(* Logix 5000 project; controller Test vendor 1 type 14 code 92 rev 33.11; software revision 33.00 *)

TASK MainTask (continuous, watchdog 500 ms) : MainProgram

MODULES
   Local : vendor 1 type 14 code 92 (ICP 0, rev 33.11)
      IN : vendor 1 type 7 code 1 (ICP 3, rev 3.2, Input RPI 20 ms)
      O : vendor 1 type 7 code 15 (ICP 2, rev 3.2, Output RPI 20 ms)
      Ethernet : 1756-ENBT (ICP 1, Ethernet 192.168.0.98, rev 6.4)
         IOLM1 : DXM (Ethernet 192.168.0.12, rev 2.22, StandardDataDriven RPI 20 ms)
END_MODULES

TYPE Banner_IOL_Port_v4 :   // UDT that has all of the data items necessary to communicate with a specific Port on a IO-Link Master
STRUCT
   Port_Controlled : INT;   // Each bit represents a port on an IO-Link Master. Set to 1 to tell AOI to control that port.
   Port_Activate : INT;   // Each bit represents a port on an IO-Link Master. When ON that port will process any commands in queue.
   Port_Read : INT;   // Each bit represents a port on an IO-Link Master. Used to determine when device AOI has requested a Read command.
   Port_Write : INT;   // Each bit represents a port on an IO-Link Master. Used to determine when device AOI has requested a Write command.
   Port_RW_Complete : INT;   // Each bit represents a port on an IO-Link Master. Tells device AOI that Read or Write request has been completed.
   Port_Device_Read : INT;
   Data_Transfer : SINT[190];   // Array to transfer data from IO-Master to device AOIs.
END_STRUCT
END_TYPE

TYPE Banner_IOLM_EL_v4 :   // Error Log for Messages to IOLM.
STRUCT
   RW : SINT;   // 0 = Read, 1 = Write.
   Port : SINT;   // Port number that generated error.
   Index : INT;   // IO-Link Index for generated error.
END_STRUCT
END_TYPE

TYPE Banner_IOLM_v4 :   // UDT to control IO-Link Masters.
STRUCT
   Message_Source_Data : SINT[190];
   Message_Destination_Data : SINT[190];
   Error_Log : Banner_IOLM_EL_v4[10];
   Error_Write_Retry : BOOL;
   Num_Error_MSGS : DINT;
   IO_Link_Master_Busy : BOOL;   // 0 = While waiting for a command, 1 = Processing command
   AOI_Reset : BOOL;
   Port_Data : Banner_IOL_Port_v4;   // All of the necessary data to work with the various ports of the IO-Link Master.
   Halt_Operation : BOOL;   // When parameter is 1 the AOI is halted as next available time frame.
   AOI_Halted : BOOL;   // AOI is in standby mode until Halt Operation tag is set back to 0.
END_STRUCT
END_TYPE

TYPE Banner_S15C_MGN_PDIO_v4 :   // UDT with all of the variables needed to control an IO-Link S15C MGN.
STRUCT
   Read : Banner_S15C_MGN_Read_DS_v4;   // English Data Set
   Write : Banner_S15C_MGN_Write_DS_v4;   // Metric Data Set
   DTI : SINT[32];   // Array with Raw Process data being transferred into AOI.
   DTO : SINT[32];   // Array with Raw Process data being transferred into AOI.
END_STRUCT
END_TYPE

TYPE Banner_S15C_MGN_RD_v4 :   // All of the read parameters for a S15C.
STRUCT
   Master_Cycle_Time : INT;
   Min_Cycle_Time : INT;
   M_Sequence_Capability : INT;
   IO_Link_Version_ID : INT;
   Process_Data_Input_Length : INT;
   Process_Data_Output_Length : INT;
   Combined_Vendor_ID : DINT;   // IO-Link Vendor ID
   Vendor_ID1 : INT;
   Vendor_ID2 : INT;
   Combined_Device_ID : DINT;   // IO-Link Device ID
   Device_ID1 : INT;
   Device_ID2 : INT;
   Device_ID3 : INT;
   Serial_Number : STRING;
   Product_Name : STRING;
END_STRUCT
END_TYPE

TYPE Banner_S15C_MGN_Read_DS_v4 :
STRUCT
   Read_Data_Set : SINT;
   Read_Success : SINT;
   Write_Success : SINT;
   Register_Verify : SINT;
   Counter_Value : INT;
   Read_Regs : DINT[16];
END_STRUCT
END_TYPE

TYPE Banner_S15C_MGN_v4 :   // All of the parameters for a S15C.
STRUCT
   Initial_Global_Read : BOOL;   // Determines if all of the IO-Link data has been read into the PLC yet
   Command : INT;   // Value placed in here will activate a read or write to a specifc IO-Link Index
   Read : Banner_S15C_MGN_RD_v4;   // Read Only Data
   Write : Banner_S15C_MGN_WD_v4;   // Write Data
   Archive : Banner_S15C_MGN_WD_v4;   // Archive Data
   Reset : BOOL;   // Resets AOI. This will force a complete parameter read of the sensor.
END_STRUCT
END_TYPE

TYPE Banner_S15C_MGN_WD_v4 :   // UDT that stores the Write Data for a S15C.
STRUCT
   System_Command : INT;   // See IODD file for list of commands that can be activated via the System Command interface
   Parameter_Access_Lock : SINT;   // Write access to all parameters is prohibited while value is 1. Only this parameter can be adjusted when value is 1.
   Data_Storage_Lock : SINT;   // Automatic data storage is disabled when this value is equal to 1. Read access is not affected.
   Local_Parameterization_Lock : SINT;   // Parameterization via local control elements on device is disabled.
   Local_User_Interface_Lock : SINT;   // Operation of local user interface is disabled.
   Modbus_Address : DINT;   // 0 to 255
   Modbus_Baud_Rate : DINT;   // 1 to 65535
   Modbus_Parity : DINT;   // 0 to 2
   Modbus_Stop_Bits : DINT;   // 0 to 2
   Modbus_Compliance_Mode : DINT;   // 0 to 4
   RRS : Banner_S15C_RRSS_v4[4];   // Read Register Sets
   WRS : Banner_S15C_WRSS_v4[16];   // Write Registers Set
END_STRUCT
END_TYPE

TYPE Banner_S15C_MGN_Write_DS_v4 :
STRUCT
   Set_to_Read : SINT;
   Write_Regs : DINT[16];
END_STRUCT
END_TYPE

TYPE Banner_S15C_RRSS_v4 :   // Read Register Set Settings
STRUCT
   MB_Reg : DINT[16];   // Index 1 through 15 are used to store the Modbus Registers
END_STRUCT
END_TYPE

TYPE Banner_S15C_WRSS_v4 :   // Write Register Set Settings
STRUCT
   MB_Reg : DINT;   // Index 1 through 15 are used to store the Modbus registers
   MB_Update_Type : SINT;   // Index 1 through 15 used to store the Modbus registers update type
   MB_Check_Result : SINT;   // Index 1 through 15 used to store the Modbus Check Result
   MB_Write_Cmd_Type : SINT;   // Index 1 through 15 used to store the Write Command type
END_STRUCT
END_TYPE

ADD_ON_INSTRUCTION Banner_DXMR90_IOLM_v4   (* revision 4.1, vendor Banner Engineering *)
// AOI that controls a Banner IO-Link Master with Banner devices.
// Revision note:
// Revised operational order for ISDU write.
VAR_IN_OUT
   IOLM : Banner_IOLM_v4; {required}
END_VAR
VAR
   Lock : DINT; {access None}
   Byte_Length : SINT; {access None}
   Current_Port : INT; {access None}   // Current port to communicate with via the IO-Link Master.
   Timer : TIMER := (PRE := 500); {access None}
   Error_Index : DINT; {access None}
   Timer2 : TIMER := (PRE := 5000); {access None}
   Temp_Index : INT; {access None}
   ErrCount : DINT; {access None}
   Timer4 : TIMER := (PRE := 2000); {access None}
   Timer5 : TIMER := (PRE := 2000); {access None}
   Timer3 : TIMER := (PRE := 2000); {access None}
   Timer6 : TIMER := (PRE := 3000); {access None}
   Timer7 : TIMER := (PRE := 3000); {access None}
END_VAR

ROUTINE Logic   (* ladder *)
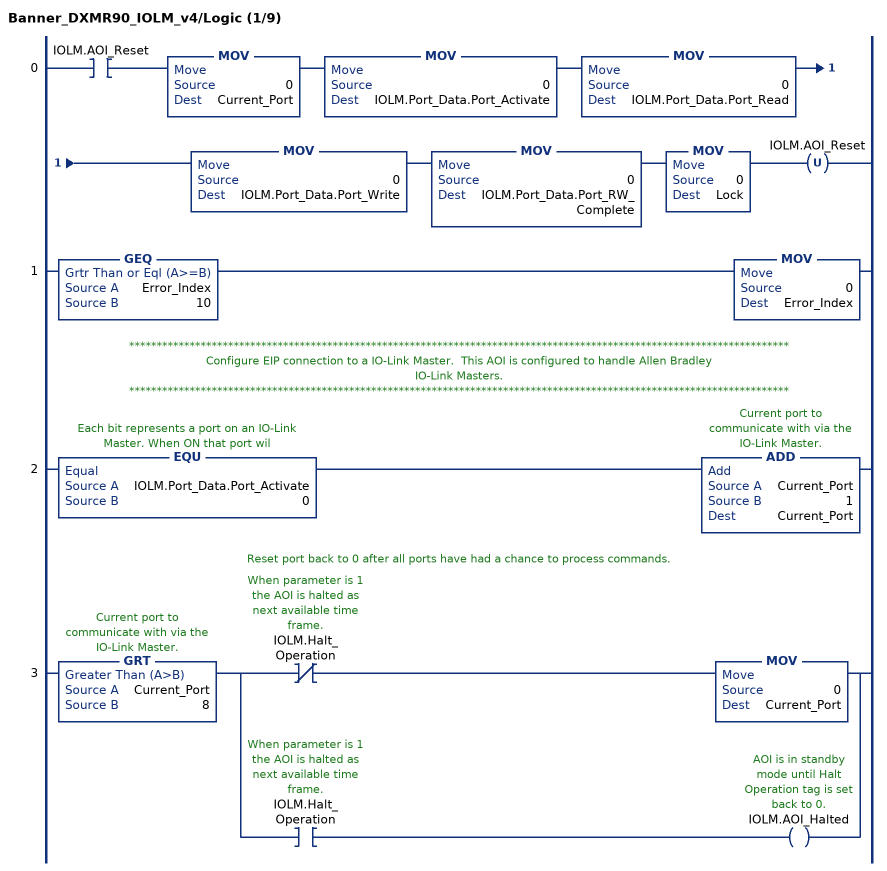
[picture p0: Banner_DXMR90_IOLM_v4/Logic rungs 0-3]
   0: XIC(IOLM.AOI_Reset)MOV(0,Current_Port)MOV(0,IOLM.Port_Data.Port_Activate)MOV(0,IOLM.Port_Data.Port_Read)MOV(0,IOLM.Port_Data.Port_Write)MOV(0,IOLM.Port_Data.Port_RW_Complete)MOV(0,Lock)OTU(IOLM.AOI_Reset);
   1: GEQ(Error_Index,10)MOV(0,Error_Index);
   // ************************************************************************************************************************
   // Configure EIP connection to a IO-Link Master.  This AOI is configured to handle Allen Bradley
   // IO-Link Masters.
   // ************************************************************************************************************************
   2: EQU(IOLM.Port_Data.Port_Activate,0)ADD(Current_Port,1,Current_Port);
   // Reset port back to 0 after all ports have had a chance to process commands.
   3: GRT(Current_Port,8)[XIO(IOLM.Halt_Operation) MOV(0,Current_Port) ,XIC(IOLM.Halt_Operation) OTE(IOLM.AOI_Halted) ];
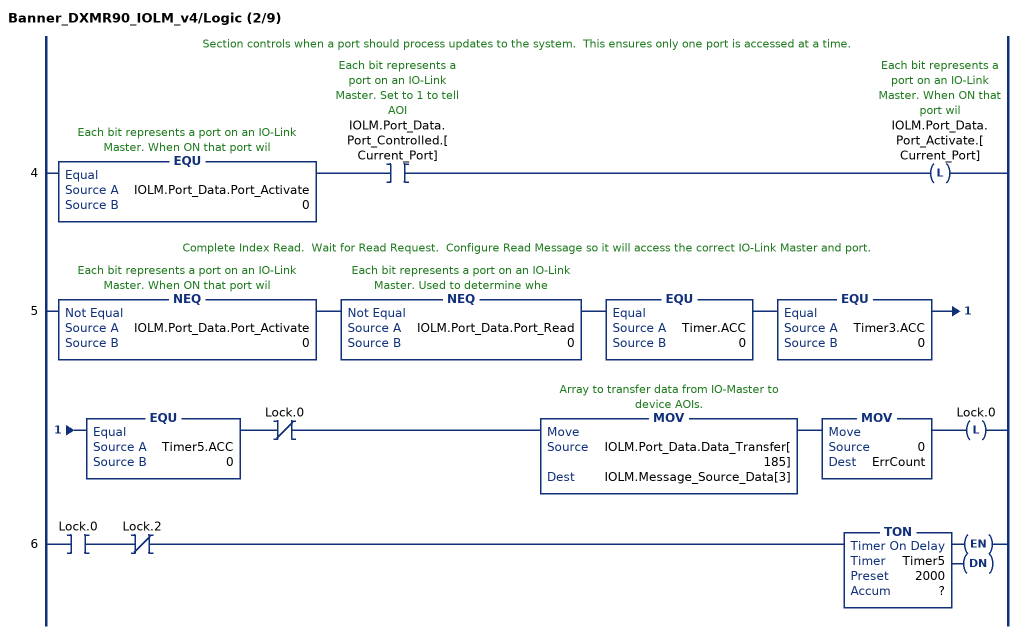
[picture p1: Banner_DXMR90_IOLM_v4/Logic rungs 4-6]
   // Section controls when a port should process updates to the system.  This ensures only one port is accessed at a time.
   4: EQU(IOLM.Port_Data.Port_Activate,0)XIC(IOLM.Port_Data.Port_Controlled.[Current_Port])OTL(IOLM.Port_Data.Port_Activate.[Current_Port]);
   // Complete Index Read.  Wait for Read Request.  Configure Read Message so it will access the correct IO-Link Master and port.
   5: NEQ(IOLM.Port_Data.Port_Activate,0)NEQ(IOLM.Port_Data.Port_Read,0)EQU(Timer.ACC,0)EQU(Timer3.ACC,0)EQU(Timer5.ACC,0)XIO(Lock.0)MOV(IOLM.Port_Data.Data_Transfer[185],IOLM.Message_Source_Data[3])MOV(0,ErrCount)OTL(Lock.0);
   6: XIC(Lock.0)XIO(Lock.2)TON(Timer5,?,?);
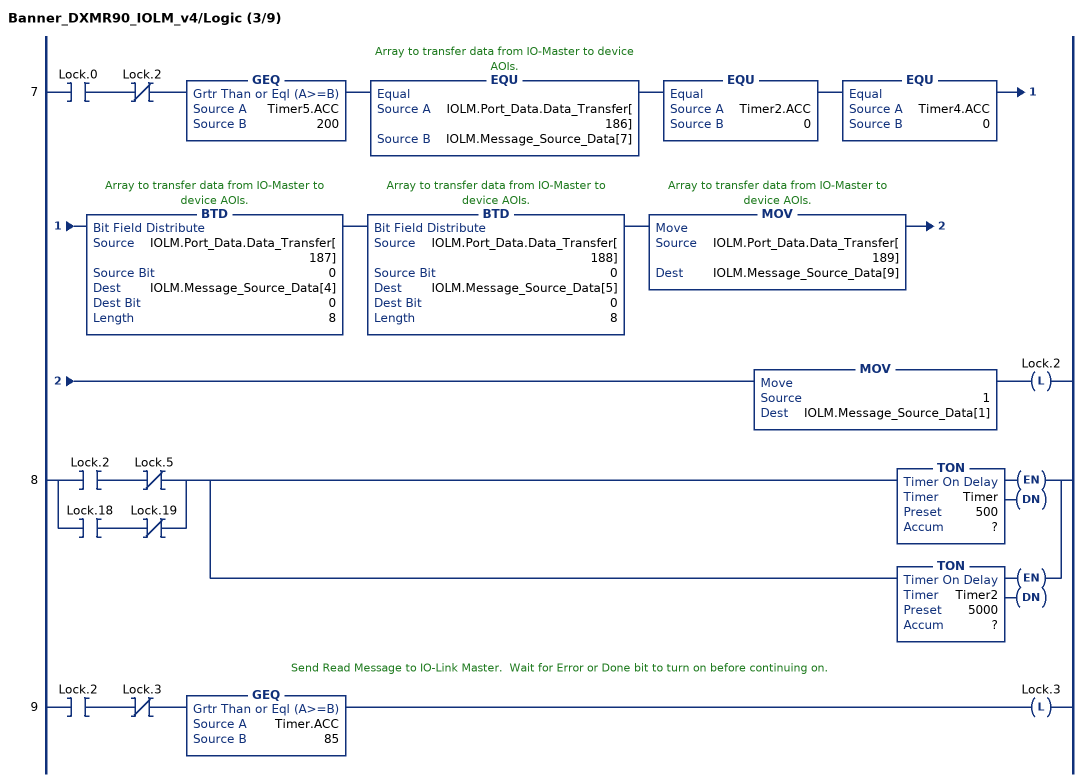
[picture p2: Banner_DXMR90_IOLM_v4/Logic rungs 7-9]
   7: XIC(Lock.0)XIO(Lock.2)GEQ(Timer5.ACC,200)EQU(IOLM.Port_Data.Data_Transfer[186],IOLM.Message_Source_Data[7])EQU(Timer2.ACC,0)EQU(Timer4.ACC,0)BTD(IOLM.Port_Data.Data_Transfer[187],0,IOLM.Message_Source_Data[4],0,8)BTD(IOLM.Port_Data.Data_Transfer[188],0,IOLM.Message_Source_Data[5],0,8)MOV(IOLM.Port_Data.Data_Transfer[189],IOLM.Message_Source_Data[9])MOV(1,IOLM.Message_Source_Data[1])OTL(Lock.2);
   8: [XIC(Lock.2) XIO(Lock.5) ,XIC(Lock.18) XIO(Lock.19) ][TON(Timer,?,?) ,TON(Timer2,?,?) ];
   // Send Read Message to IO-Link Master.  Wait for Error or Done bit to turn on before continuing on.
   9: XIC(Lock.2)XIO(Lock.3)GEQ(Timer.ACC,85)OTL(Lock.3);
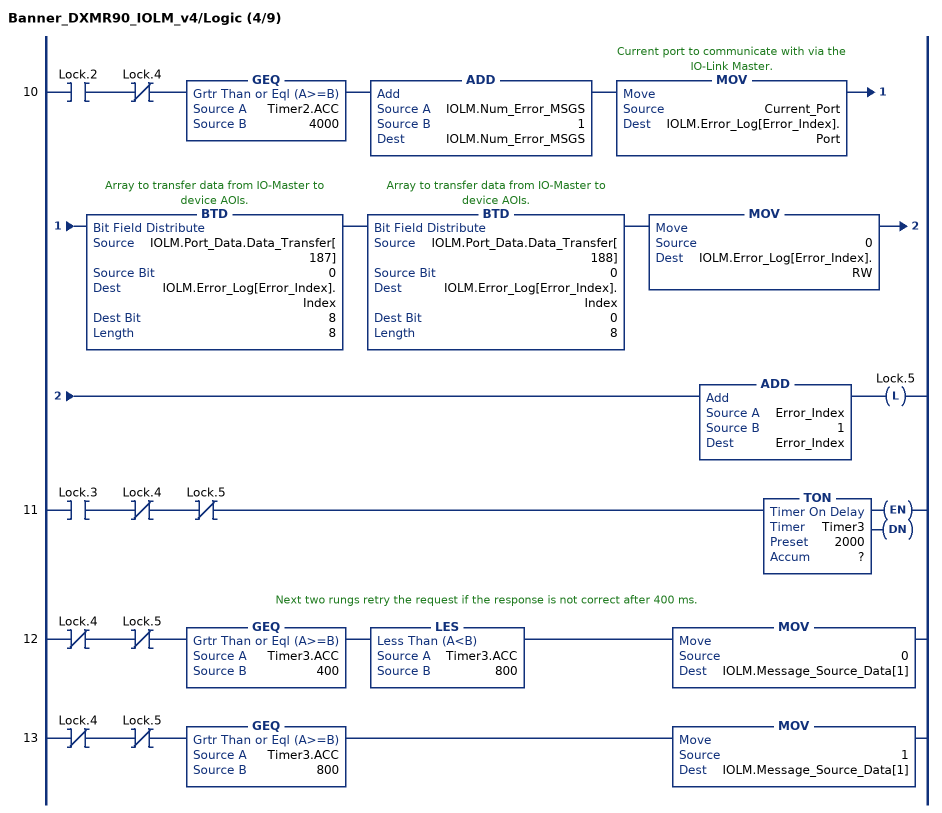
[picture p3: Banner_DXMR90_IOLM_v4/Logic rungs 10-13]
   10: XIC(Lock.2)XIO(Lock.4)GEQ(Timer2.ACC,4000)ADD(IOLM.Num_Error_MSGS,1,IOLM.Num_Error_MSGS)MOV(Current_Port,IOLM.Error_Log[Error_Index].Port)BTD(IOLM.Port_Data.Data_Transfer[187],0,IOLM.Error_Log[Error_Index].Index,8,8)BTD(IOLM.Port_Data.Data_Transfer[188],0,IOLM.Error_Log[Error_Index].Index,0,8)MOV(0,IOLM.Error_Log[Error_Index].RW)ADD(Error_Index,1,Error_Index)OTL(Lock.5);
   11: XIC(Lock.3)XIO(Lock.4)XIO(Lock.5)TON(Timer3,?,?);
   // Next two rungs retry the request if the response is not correct after 400 ms.
   12: XIO(Lock.4)XIO(Lock.5)GEQ(Timer3.ACC,400)LES(Timer3.ACC,800)MOV(0,IOLM.Message_Source_Data[1]);
   13: XIO(Lock.4)XIO(Lock.5)GEQ(Timer3.ACC,800)MOV(1,IOLM.Message_Source_Data[1]);
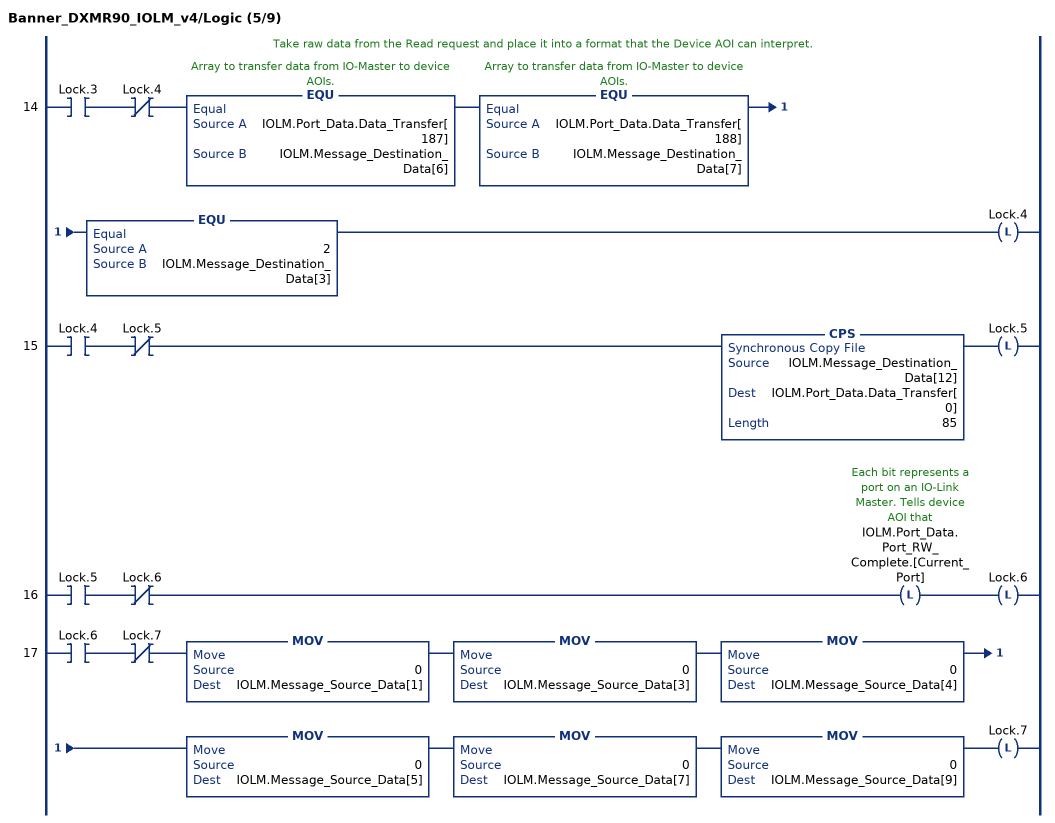
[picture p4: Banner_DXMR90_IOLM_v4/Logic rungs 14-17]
   // Take raw data from the Read request and place it into a format that the Device AOI can interpret.
   14: XIC(Lock.3)XIO(Lock.4)EQU(IOLM.Port_Data.Data_Transfer[187],IOLM.Message_Destination_Data[6])EQU(IOLM.Port_Data.Data_Transfer[188],IOLM.Message_Destination_Data[7])EQU(2,IOLM.Message_Destination_Data[3])OTL(Lock.4);
   15: XIC(Lock.4)XIO(Lock.5)CPS(IOLM.Message_Destination_Data[12],IOLM.Port_Data.Data_Transfer[0],85)OTL(Lock.5);
   16: XIC(Lock.5)XIO(Lock.6)OTL(IOLM.Port_Data.Port_RW_Complete.[Current_Port])OTL(Lock.6);
   17: XIC(Lock.6)XIO(Lock.7)MOV(0,IOLM.Message_Source_Data[1])MOV(0,IOLM.Message_Source_Data[3])MOV(0,IOLM.Message_Source_Data[4])MOV(0,IOLM.Message_Source_Data[5])MOV(0,IOLM.Message_Source_Data[7])MOV(0,IOLM.Message_Source_Data[9])OTL(Lock.7);
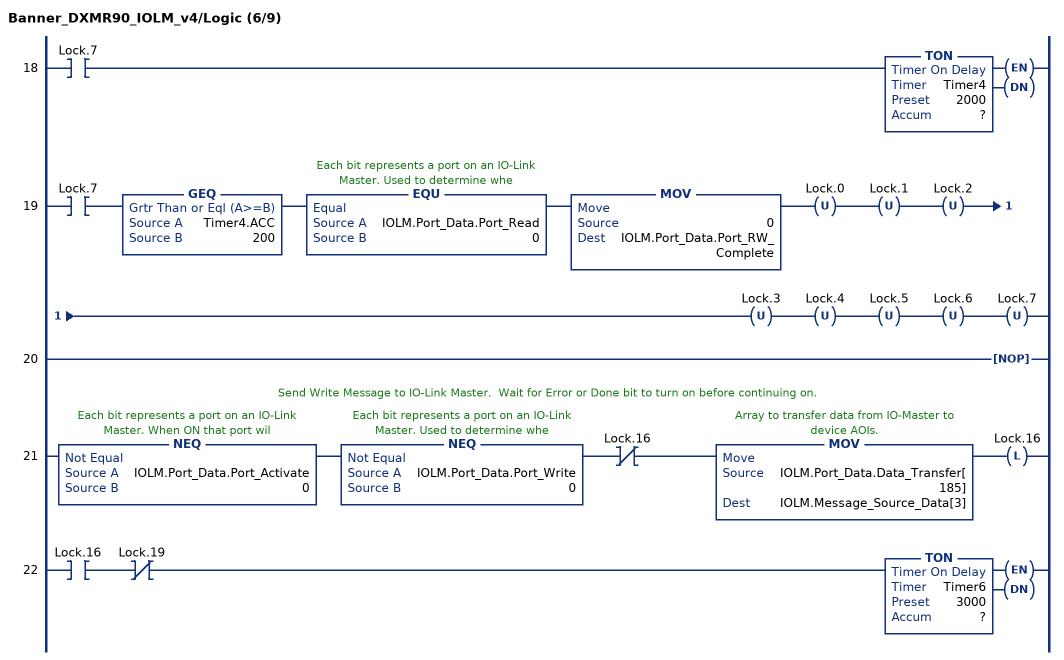
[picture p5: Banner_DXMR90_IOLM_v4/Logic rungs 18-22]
   18: XIC(Lock.7)TON(Timer4,?,?);
   19: XIC(Lock.7)GEQ(Timer4.ACC,200)EQU(IOLM.Port_Data.Port_Read,0)MOV(0,IOLM.Port_Data.Port_RW_Complete)OTU(Lock.0)OTU(Lock.1)OTU(Lock.2)OTU(Lock.3)OTU(Lock.4)OTU(Lock.5)OTU(Lock.6)OTU(Lock.7);
   20: NOP();
   // Send Write Message to IO-Link Master.  Wait for Error or Done bit to turn on before continuing on.
   21: NEQ(IOLM.Port_Data.Port_Activate,0)NEQ(IOLM.Port_Data.Port_Write,0)XIO(Lock.16)MOV(IOLM.Port_Data.Data_Transfer[185],IOLM.Message_Source_Data[3])OTL(Lock.16);
   22: XIC(Lock.16)XIO(Lock.19)TON(Timer6,?,?);
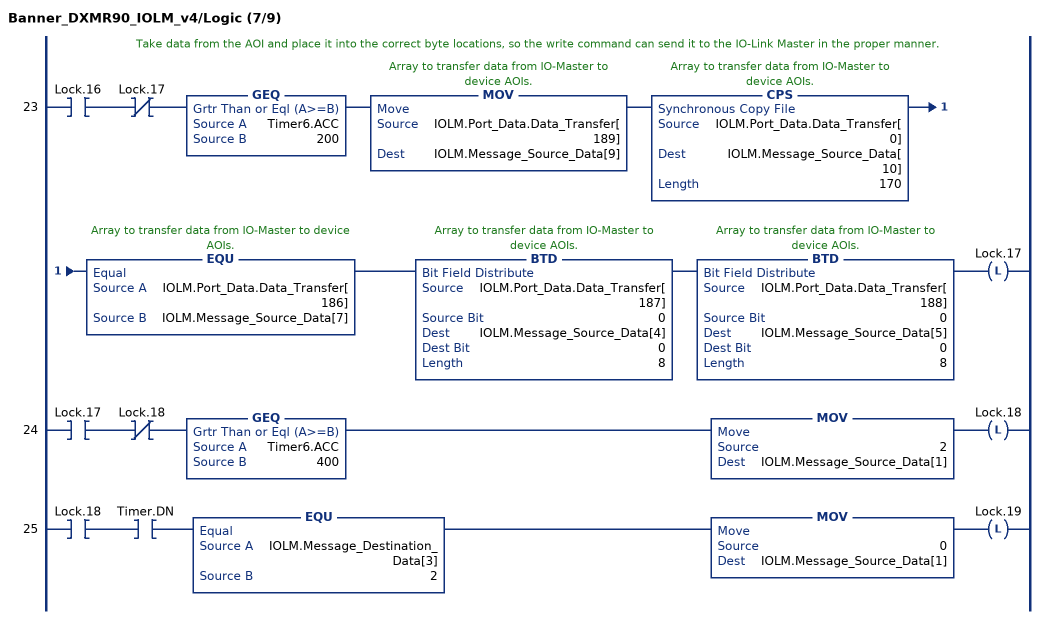
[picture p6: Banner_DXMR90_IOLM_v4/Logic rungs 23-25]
   // Take data from the AOI and place it into the correct byte locations, so the write command can send it to the IO-Link Master in the proper manner.
   23: XIC(Lock.16)XIO(Lock.17)GEQ(Timer6.ACC,200)MOV(IOLM.Port_Data.Data_Transfer[189],IOLM.Message_Source_Data[9])CPS(IOLM.Port_Data.Data_Transfer[0],IOLM.Message_Source_Data[10],170)EQU(IOLM.Port_Data.Data_Transfer[186],IOLM.Message_Source_Data[7])BTD(IOLM.Port_Data.Data_Transfer[187],0,IOLM.Message_Source_Data[4],0,8)BTD(IOLM.Port_Data.Data_Transfer[188],0,IOLM.Message_Source_Data[5],0,8)OTL(Lock.17);
   24: XIC(Lock.17)XIO(Lock.18)GEQ(Timer6.ACC,400)MOV(2,IOLM.Message_Source_Data[1])OTL(Lock.18);
   25: XIC(Lock.18)XIC(Timer.DN)EQU(IOLM.Message_Destination_Data[3],2)MOV(0,IOLM.Message_Source_Data[1])OTL(Lock.19);
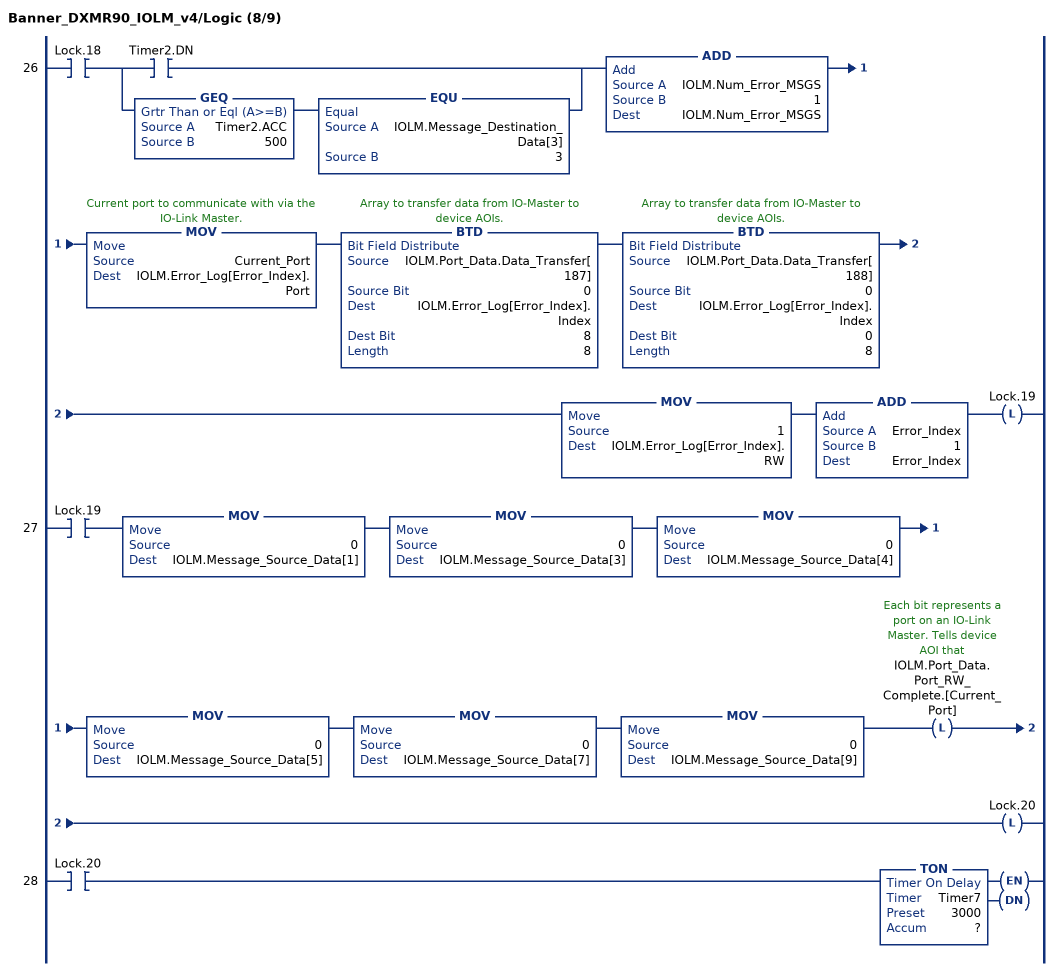
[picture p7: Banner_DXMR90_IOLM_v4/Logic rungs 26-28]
   26: XIC(Lock.18)[XIC(Timer2.DN) ,GEQ(Timer2.ACC,500) EQU(IOLM.Message_Destination_Data[3],3) ]ADD(IOLM.Num_Error_MSGS,1,IOLM.Num_Error_MSGS)MOV(Current_Port,IOLM.Error_Log[Error_Index].Port)BTD(IOLM.Port_Data.Data_Transfer[187],0,IOLM.Error_Log[Error_Index].Index,8,8)BTD(IOLM.Port_Data.Data_Transfer[188],0,IOLM.Error_Log[Error_Index].Index,0,8)MOV(1,IOLM.Error_Log[Error_Index].RW)ADD(Error_Index,1,Error_Index)OTL(Lock.19);
   27: XIC(Lock.19)MOV(0,IOLM.Message_Source_Data[1])MOV(0,IOLM.Message_Source_Data[3])MOV(0,IOLM.Message_Source_Data[4])MOV(0,IOLM.Message_Source_Data[5])MOV(0,IOLM.Message_Source_Data[7])MOV(0,IOLM.Message_Source_Data[9])OTL(IOLM.Port_Data.Port_RW_Complete.[Current_Port])OTL(Lock.20);
   28: XIC(Lock.20)TON(Timer7,?,?);
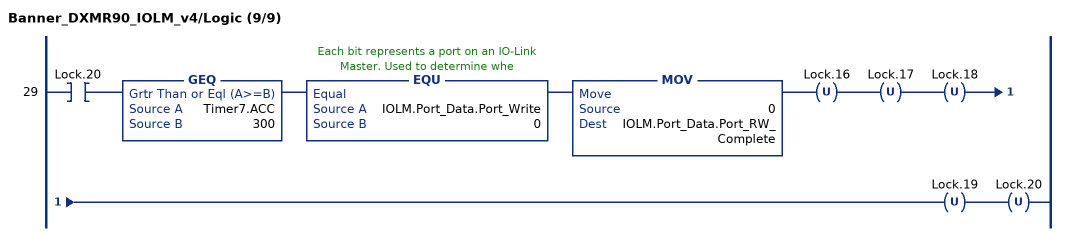
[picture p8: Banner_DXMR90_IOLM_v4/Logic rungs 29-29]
   29: XIC(Lock.20)GEQ(Timer7.ACC,300)EQU(IOLM.Port_Data.Port_Write,0)MOV(0,IOLM.Port_Data.Port_RW_Complete)OTU(Lock.16)OTU(Lock.17)OTU(Lock.18)OTU(Lock.19)OTU(Lock.20);
END_ROUTINE
END_ADD_ON_INSTRUCTION

ADD_ON_INSTRUCTION Banner_S15C_MGN_Param_v4   (* revision 4.0, vendor Banner Engineering *)
// AOI to read and write parameter data to an IO-Link S15C.
VAR_IN_OUT
   S15C : Banner_S15C_MGN_v4; {required}
   Port_Data : Banner_IOL_Port_v4; {required}
END_VAR
VAR_INPUT
   Port : DINT; {required}
END_VAR
VAR
   Local_Control : DINT; {access None}
   Global_Read_Command_Value : INT; {access None}
   Global_Write_Command_Value : INT; {access None}
   Error_Generated : BOOL; {access None}
   Command_Being_Processed : BOOL; {access None}
   Index_Write_Inprocess : INT; {access None}
   Index_Write_Control : INT; {access None}
   Update_Archive : BOOL; {access None}
   Inprocess_Index : DINT; {access None}
   RRS_Index0 : SINT; {access None}
   WRS_Index1 : SINT; {access None}
   WRS_Index0 : SINT; {access None}
   RRS_Index2 : SINT; {access None}
   RRS_Index1 : SINT; {access None}
   RRS_Index3 : SINT; {access None}
   WRS_Index2 : SINT; {access None}
   WRS_Index3 : SINT; {access None}
   WRS_Index4 : SINT; {access None}
   DoNotRun : BOOL; {access None}
   WR_Control : DINT; {access None}
END_VAR

ROUTINE Logic   (* ladder *)
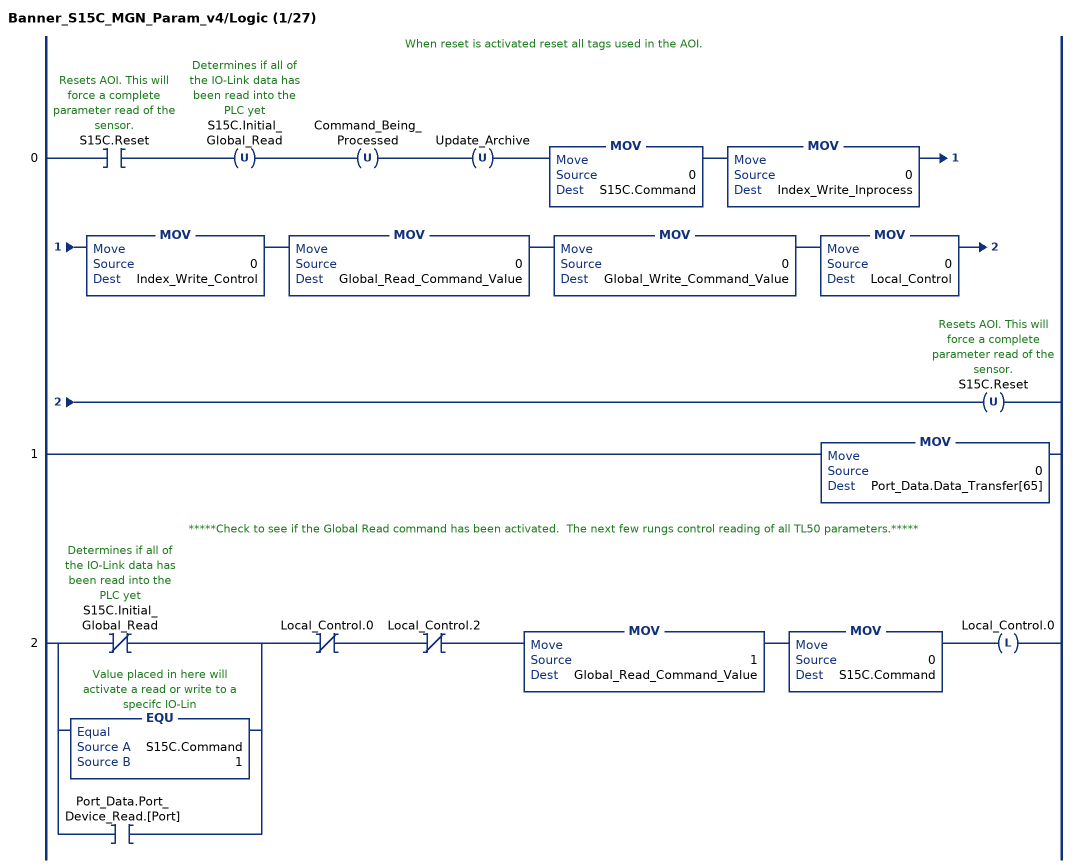
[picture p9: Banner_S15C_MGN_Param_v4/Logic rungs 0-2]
   // When reset is activated reset all tags used in the AOI.
   0: XIC(S15C.Reset)OTU(S15C.Initial_Global_Read)OTU(Command_Being_Processed)OTU(Update_Archive)MOV(0,S15C.Command)MOV(0,Index_Write_Inprocess)MOV(0,Index_Write_Control)MOV(0,Global_Read_Command_Value)MOV(0,Global_Write_Command_Value)MOV(0,Local_Control)OTU(S15C.Reset);
   1: MOV(0,Port_Data.Data_Transfer[65]);
   // *****Check to see if the Global Read command has been activated.  The next few rungs control reading of all TL50 parameters.*****
   2: [XIO(S15C.Initial_Global_Read) ,EQU(S15C.Command,1) ,XIC(Port_Data.Port_Device_Read.[Port]) ]XIO(Local_Control.0)XIO(Local_Control.2)MOV(1,Global_Read_Command_Value)MOV(0,S15C.Command)OTL(Local_Control.0);
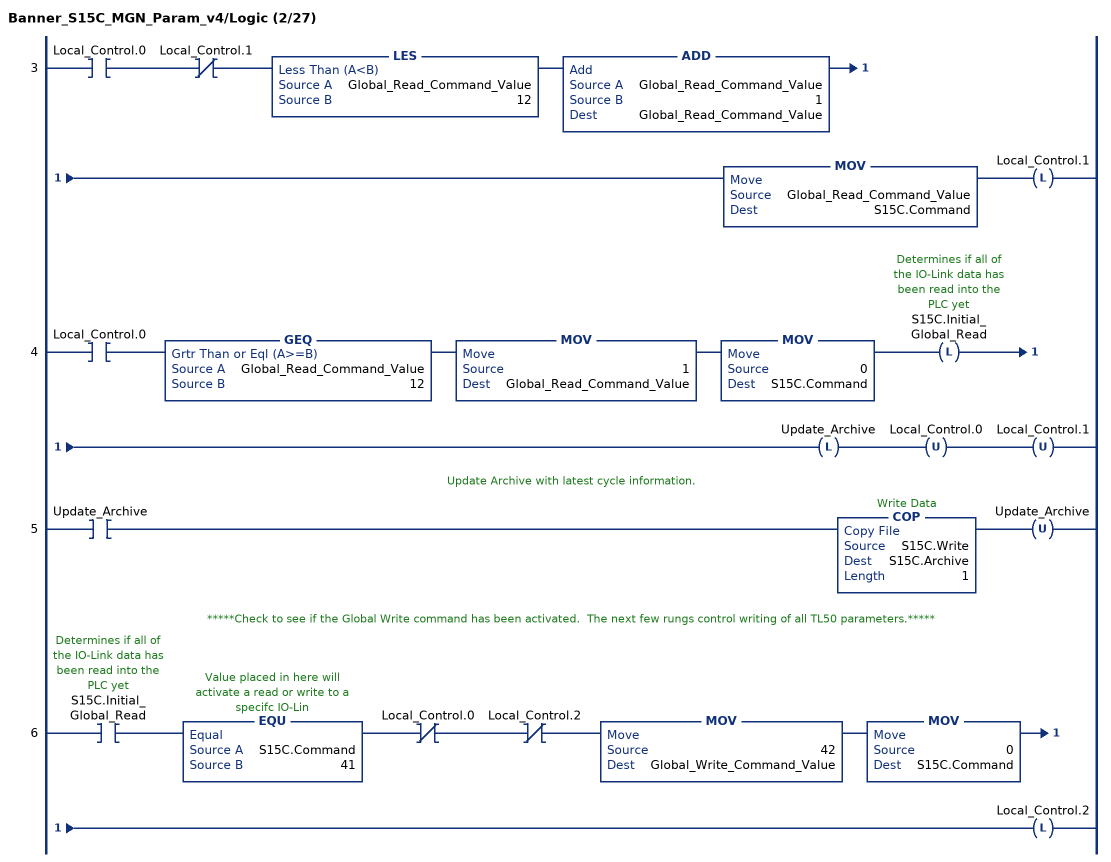
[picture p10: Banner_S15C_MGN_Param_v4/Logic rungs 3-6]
   3: XIC(Local_Control.0)XIO(Local_Control.1)LES(Global_Read_Command_Value,12)ADD(Global_Read_Command_Value,1,Global_Read_Command_Value)MOV(Global_Read_Command_Value,S15C.Command)OTL(Local_Control.1);
   4: XIC(Local_Control.0)GEQ(Global_Read_Command_Value,12)MOV(1,Global_Read_Command_Value)MOV(0,S15C.Command)OTL(S15C.Initial_Global_Read)OTL(Update_Archive)OTU(Local_Control.0)OTU(Local_Control.1);
   // Update Archive with latest cycle information.
   5: XIC(Update_Archive)COP(S15C.Write,S15C.Archive,1)OTU(Update_Archive);
   // *****Check to see if the Global Write command has been activated.  The next few rungs control writing of all TL50 parameters.*****
   6: XIC(S15C.Initial_Global_Read)EQU(S15C.Command,41)XIO(Local_Control.0)XIO(Local_Control.2)MOV(42,Global_Write_Command_Value)MOV(0,S15C.Command)OTL(Local_Control.2);
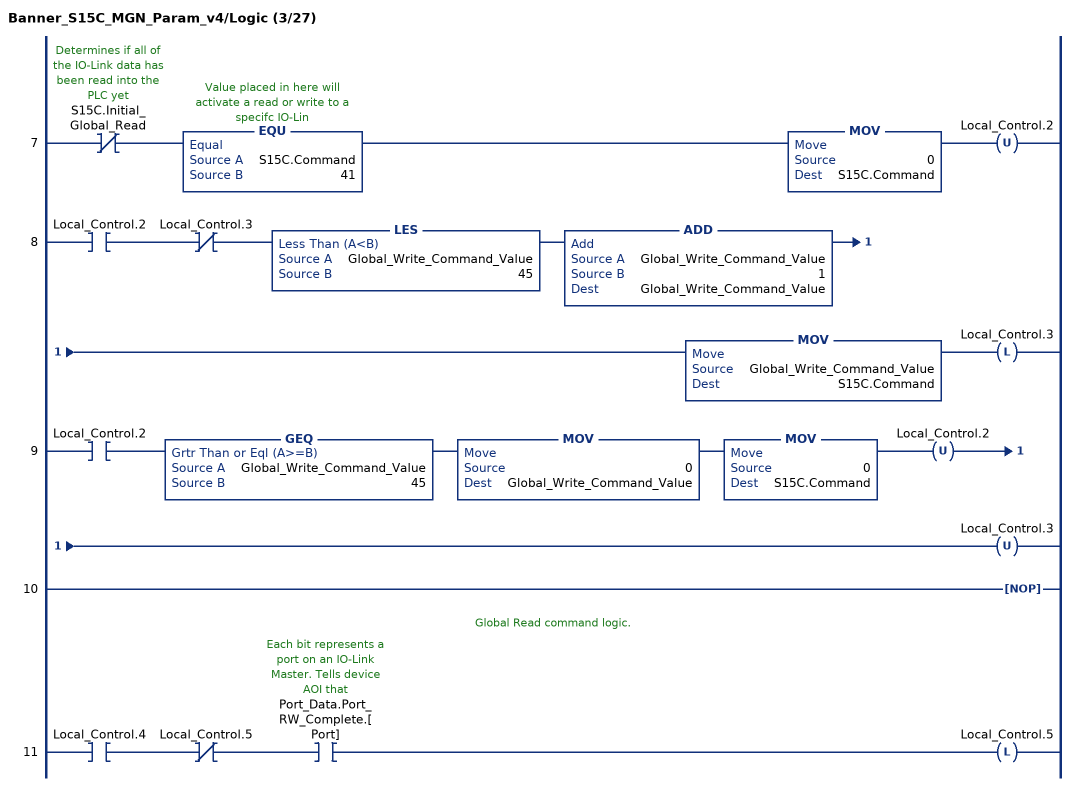
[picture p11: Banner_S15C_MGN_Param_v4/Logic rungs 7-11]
   7: XIO(S15C.Initial_Global_Read)EQU(S15C.Command,41)MOV(0,S15C.Command)OTU(Local_Control.2);
   8: XIC(Local_Control.2)XIO(Local_Control.3)LES(Global_Write_Command_Value,45)ADD(Global_Write_Command_Value,1,Global_Write_Command_Value)MOV(Global_Write_Command_Value,S15C.Command)OTL(Local_Control.3);
   9: XIC(Local_Control.2)GEQ(Global_Write_Command_Value,45)MOV(0,Global_Write_Command_Value)MOV(0,S15C.Command)OTU(Local_Control.2)OTU(Local_Control.3);
   10: NOP();
   // Global Read command logic.
   11: XIC(Local_Control.4)XIO(Local_Control.5)XIC(Port_Data.Port_RW_Complete.[Port])OTL(Local_Control.5);
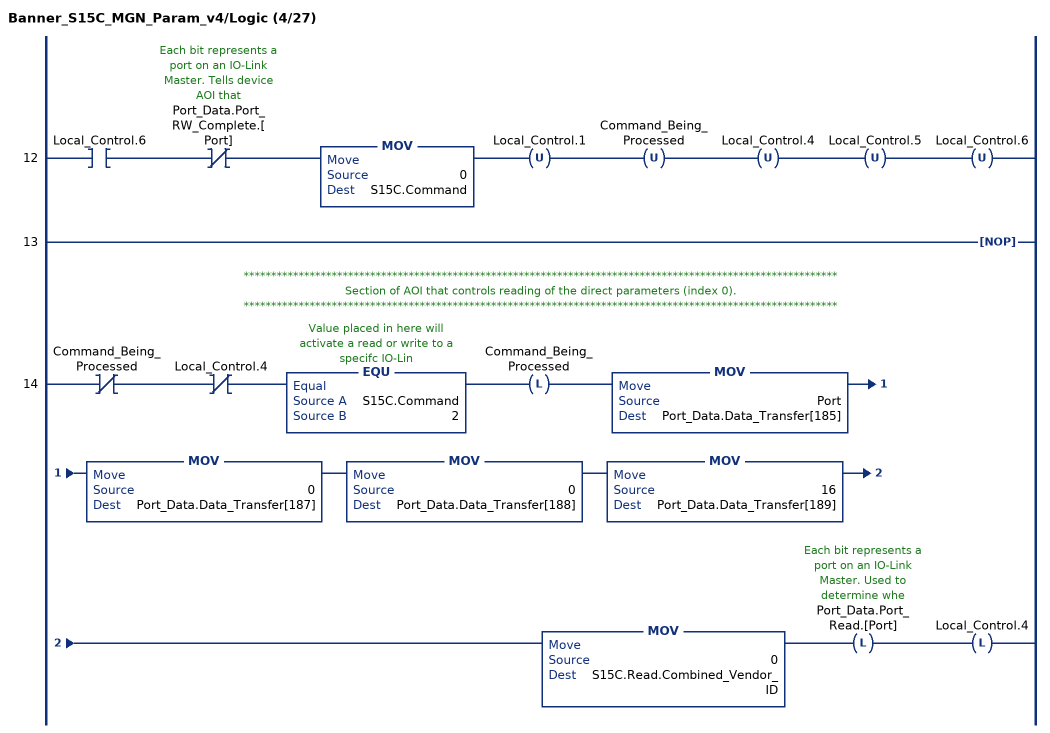
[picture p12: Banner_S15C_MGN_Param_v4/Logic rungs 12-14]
   12: XIC(Local_Control.6)XIO(Port_Data.Port_RW_Complete.[Port])MOV(0,S15C.Command)OTU(Local_Control.1)OTU(Command_Being_Processed)OTU(Local_Control.4)OTU(Local_Control.5)OTU(Local_Control.6);
   13: NOP();
   // ************************************************************************************************************
   // Section of AOI that controls reading of the direct parameters (index 0).
   // ************************************************************************************************************
   14: XIO(Command_Being_Processed)XIO(Local_Control.4)EQU(S15C.Command,2)OTL(Command_Being_Processed)MOV(Port,Port_Data.Data_Transfer[185])MOV(0,Port_Data.Data_Transfer[187])MOV(0,Port_Data.Data_Transfer[188])MOV(16,Port_Data.Data_Transfer[189])MOV(0,S15C.Read.Combined_Vendor_ID)OTL(Port_Data.Port_Read.[Port])OTL(Local_Control.4);
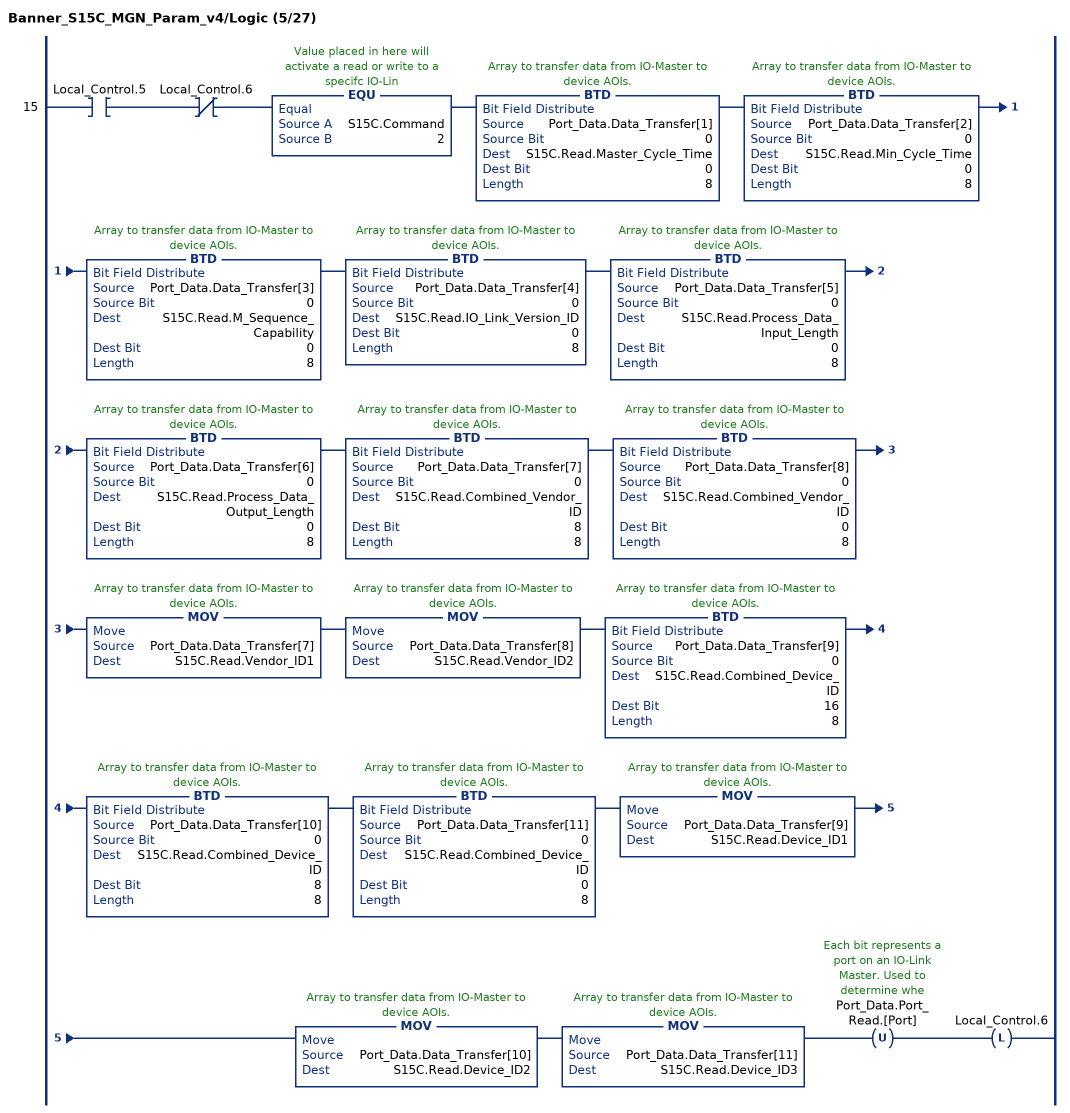
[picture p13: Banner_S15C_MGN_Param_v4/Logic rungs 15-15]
   15: XIC(Local_Control.5)XIO(Local_Control.6)EQU(S15C.Command,2)BTD(Port_Data.Data_Transfer[1],0,S15C.Read.Master_Cycle_Time,0,8)BTD(Port_Data.Data_Transfer[2],0,S15C.Read.Min_Cycle_Time,0,8)BTD(Port_Data.Data_Transfer[3],0,S15C.Read.M_Sequence_Capability,0,8)BTD(Port_Data.Data_Transfer[4],0,S15C.Read.IO_Link_Version_ID,0,8)BTD(Port_Data.Data_Transfer[5],0,S15C.Read.Process_Data_Input_Length,0,8)BTD(Port_Data.Data_Transfer[6],0,S15C.Read.Process_Data_Output_Length,0,8)BTD(Port_Data.Data_Transfer[7],0,S15C.Read.Combined_Vendor_ID,8,8)BTD(Port_Data.Data_Transfer[8],0,S15C.Read.Combined_Vendor_ID,0,8)MOV(Port_Data.Data_Transfer[7],S15C.Read.Vendor_ID1)MOV(Port_Data.Data_Transfer[8],S15C.Read.Vendor_ID2)BTD(Port_Data.Data_Transfer[9],0,S15C.Read.Combined_Device_ID,16,8)BTD(Port_Data.Data_Transfer[10],0,S15C.Read.Combined_Device_ID,8,8)BTD(Port_Data.Data_Transfer[11],0,S15C.Read.Combined_Device_ID,0,8)MOV(Port_Data.Data_Transfer[9],S15C.Read.Device_ID1)MOV(Port_Data.Data_Transfer[10],S15C.Read.Device_ID2)MOV(Port_Data.Data_Transfer[11],S15C.Read.Device_ID3)OTU(Port_Data.Port_Read.[Port])OTL(Local_Control.6);
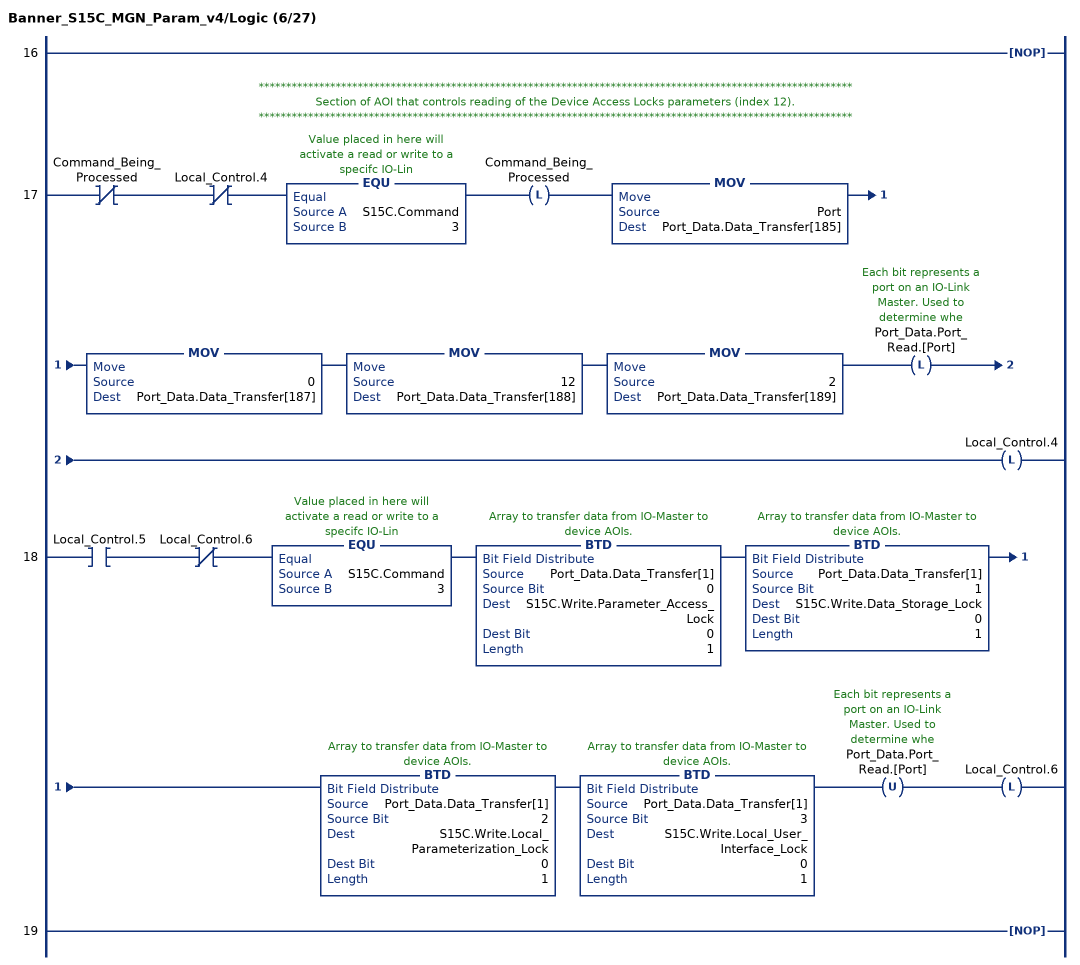
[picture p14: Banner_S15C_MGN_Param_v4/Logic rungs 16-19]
   16: NOP();
   // ************************************************************************************************************
   // Section of AOI that controls reading of the Device Access Locks parameters (index 12).
   // ************************************************************************************************************
   17: XIO(Command_Being_Processed)XIO(Local_Control.4)EQU(S15C.Command,3)OTL(Command_Being_Processed)MOV(Port,Port_Data.Data_Transfer[185])MOV(0,Port_Data.Data_Transfer[187])MOV(12,Port_Data.Data_Transfer[188])MOV(2,Port_Data.Data_Transfer[189])OTL(Port_Data.Port_Read.[Port])OTL(Local_Control.4);
   18: XIC(Local_Control.5)XIO(Local_Control.6)EQU(S15C.Command,3)BTD(Port_Data.Data_Transfer[1],0,S15C.Write.Parameter_Access_Lock,0,1)BTD(Port_Data.Data_Transfer[1],1,S15C.Write.Data_Storage_Lock,0,1)BTD(Port_Data.Data_Transfer[1],2,S15C.Write.Local_Parameterization_Lock,0,1)BTD(Port_Data.Data_Transfer[1],3,S15C.Write.Local_User_Interface_Lock,0,1)OTU(Port_Data.Port_Read.[Port])OTL(Local_Control.6);
   19: NOP();
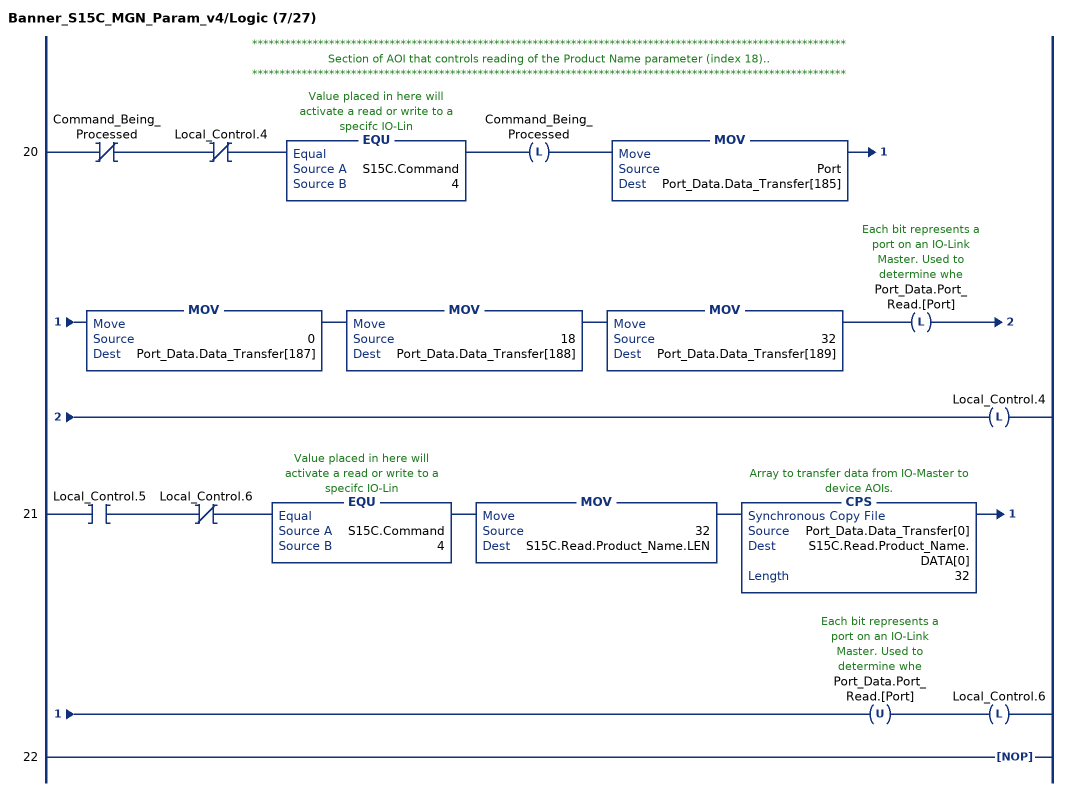
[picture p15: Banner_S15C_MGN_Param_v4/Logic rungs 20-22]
   // ************************************************************************************************************
   // Section of AOI that controls reading of the Product Name parameter (index 18)..
   // ************************************************************************************************************
   20: XIO(Command_Being_Processed)XIO(Local_Control.4)EQU(S15C.Command,4)OTL(Command_Being_Processed)MOV(Port,Port_Data.Data_Transfer[185])MOV(0,Port_Data.Data_Transfer[187])MOV(18,Port_Data.Data_Transfer[188])MOV(32,Port_Data.Data_Transfer[189])OTL(Port_Data.Port_Read.[Port])OTL(Local_Control.4);
   21: XIC(Local_Control.5)XIO(Local_Control.6)EQU(S15C.Command,4)MOV(32,S15C.Read.Product_Name.LEN)CPS(Port_Data.Data_Transfer[0],S15C.Read.Product_Name.DATA[0],32)OTU(Port_Data.Port_Read.[Port])OTL(Local_Control.6);
   22: NOP();
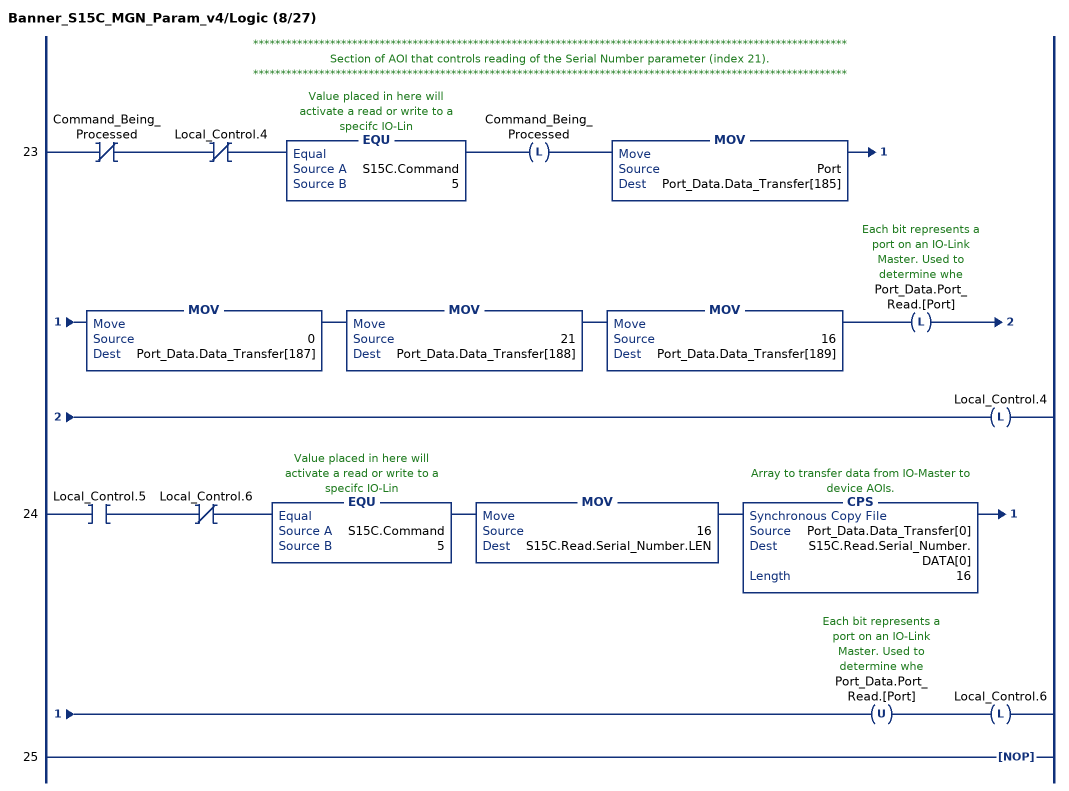
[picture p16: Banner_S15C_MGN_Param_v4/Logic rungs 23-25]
   // ************************************************************************************************************
   // Section of AOI that controls reading of the Serial Number parameter (index 21).
   // ************************************************************************************************************
   23: XIO(Command_Being_Processed)XIO(Local_Control.4)EQU(S15C.Command,5)OTL(Command_Being_Processed)MOV(Port,Port_Data.Data_Transfer[185])MOV(0,Port_Data.Data_Transfer[187])MOV(21,Port_Data.Data_Transfer[188])MOV(16,Port_Data.Data_Transfer[189])OTL(Port_Data.Port_Read.[Port])OTL(Local_Control.4);
   24: XIC(Local_Control.5)XIO(Local_Control.6)EQU(S15C.Command,5)MOV(16,S15C.Read.Serial_Number.LEN)CPS(Port_Data.Data_Transfer[0],S15C.Read.Serial_Number.DATA[0],16)OTU(Port_Data.Port_Read.[Port])OTL(Local_Control.6);
   25: NOP();
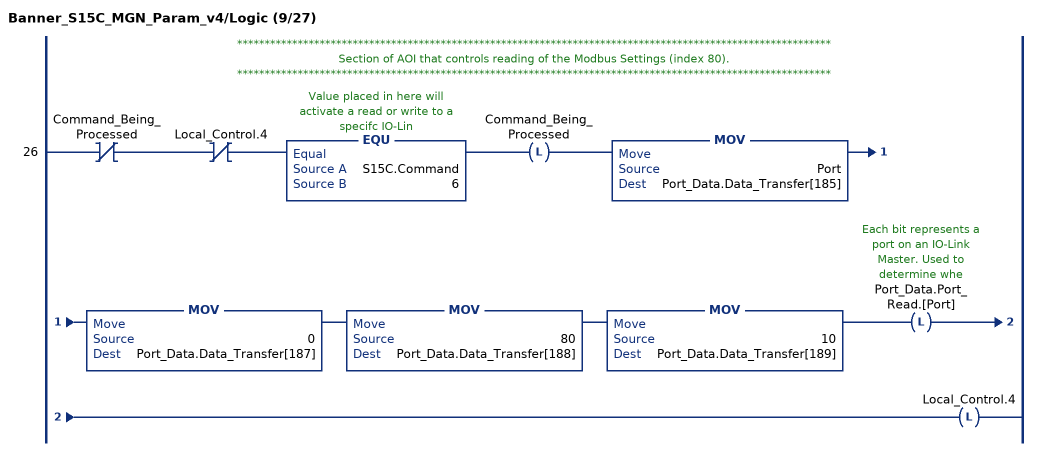
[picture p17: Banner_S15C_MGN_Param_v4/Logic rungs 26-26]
   // ************************************************************************************************************
   // Section of AOI that controls reading of the Modbus Settings (index 80).
   // ************************************************************************************************************
   26: XIO(Command_Being_Processed)XIO(Local_Control.4)EQU(S15C.Command,6)OTL(Command_Being_Processed)MOV(Port,Port_Data.Data_Transfer[185])MOV(0,Port_Data.Data_Transfer[187])MOV(80,Port_Data.Data_Transfer[188])MOV(10,Port_Data.Data_Transfer[189])OTL(Port_Data.Port_Read.[Port])OTL(Local_Control.4);
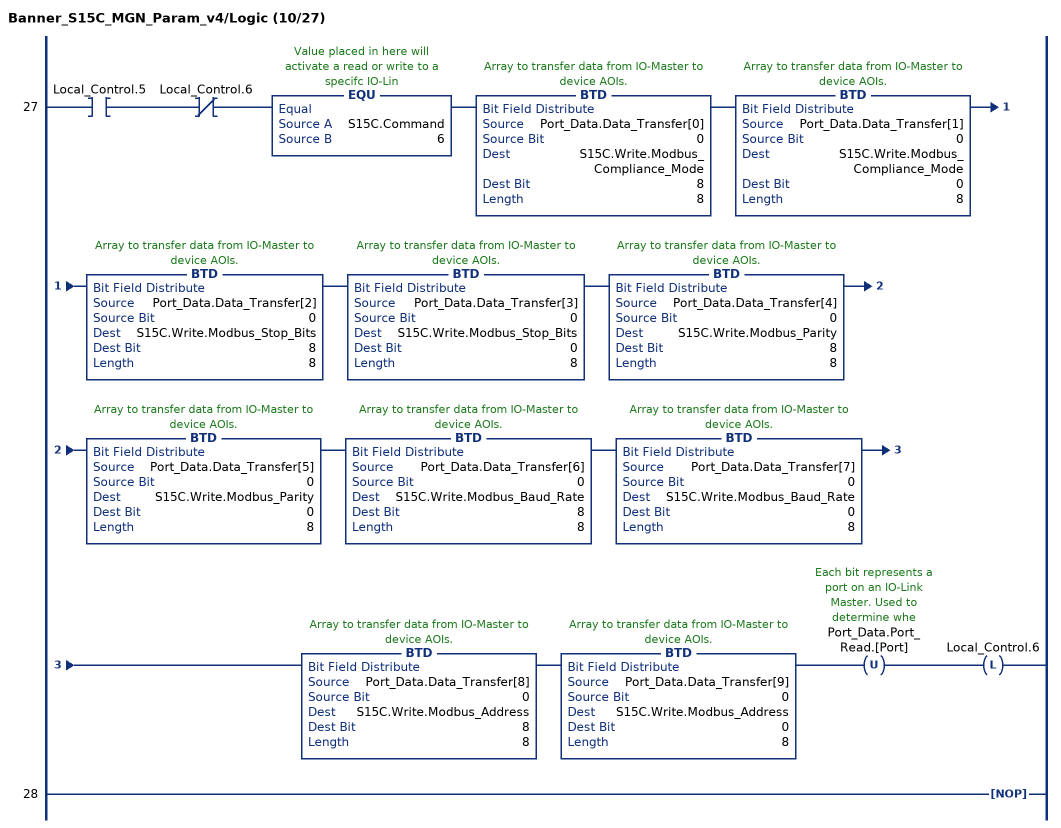
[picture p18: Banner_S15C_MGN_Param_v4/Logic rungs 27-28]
   27: XIC(Local_Control.5)XIO(Local_Control.6)EQU(S15C.Command,6)BTD(Port_Data.Data_Transfer[0],0,S15C.Write.Modbus_Compliance_Mode,8,8)BTD(Port_Data.Data_Transfer[1],0,S15C.Write.Modbus_Compliance_Mode,0,8)BTD(Port_Data.Data_Transfer[2],0,S15C.Write.Modbus_Stop_Bits,8,8)BTD(Port_Data.Data_Transfer[3],0,S15C.Write.Modbus_Stop_Bits,0,8)BTD(Port_Data.Data_Transfer[4],0,S15C.Write.Modbus_Parity,8,8)BTD(Port_Data.Data_Transfer[5],0,S15C.Write.Modbus_Parity,0,8)BTD(Port_Data.Data_Transfer[6],0,S15C.Write.Modbus_Baud_Rate,8,8)BTD(Port_Data.Data_Transfer[7],0,S15C.Write.Modbus_Baud_Rate,0,8)BTD(Port_Data.Data_Transfer[8],0,S15C.Write.Modbus_Address,8,8)BTD(Port_Data.Data_Transfer[9],0,S15C.Write.Modbus_Address,0,8)OTU(Port_Data.Port_Read.[Port])OTL(Local_Control.6);
   28: NOP();
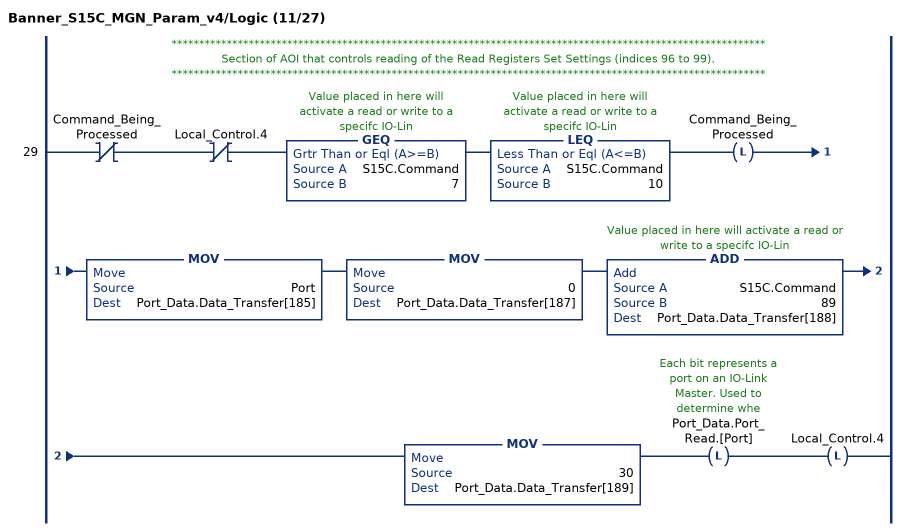
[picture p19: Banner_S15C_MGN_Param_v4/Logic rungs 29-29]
   // ************************************************************************************************************
   // Section of AOI that controls reading of the Read Registers Set Settings (indices 96 to 99).
   // ************************************************************************************************************
   29: XIO(Command_Being_Processed)XIO(Local_Control.4)GEQ(S15C.Command,7)LEQ(S15C.Command,10)OTL(Command_Being_Processed)MOV(Port,Port_Data.Data_Transfer[185])MOV(0,Port_Data.Data_Transfer[187])ADD(S15C.Command,89,Port_Data.Data_Transfer[188])MOV(30,Port_Data.Data_Transfer[189])OTL(Port_Data.Port_Read.[Port])OTL(Local_Control.4);
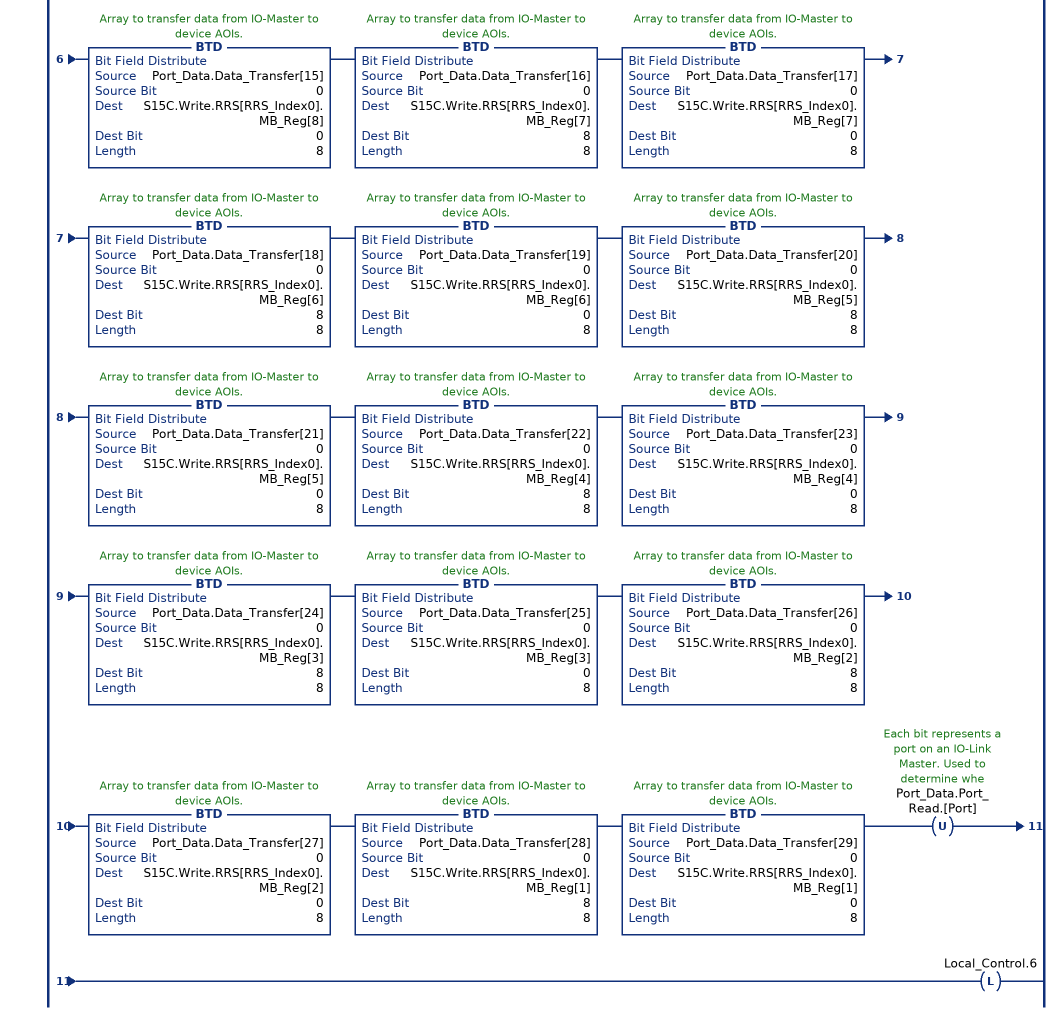
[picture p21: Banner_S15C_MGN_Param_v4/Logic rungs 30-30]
   30: XIC(Local_Control.5)XIO(Local_Control.6)GEQ(S15C.Command,7)LEQ(S15C.Command,10)SUB(S15C.Command,7,RRS_Index0)BTD(Port_Data.Data_Transfer[0],0,S15C.Write.RRS[RRS_Index0].MB_Reg[15],8,8)BTD(Port_Data.Data_Transfer[1],0,S15C.Write.RRS[RRS_Index0].MB_Reg[15],0,8)BTD(Port_Data.Data_Transfer[2],0,S15C.Write.RRS[RRS_Index0].MB_Reg[14],8,8)BTD(Port_Data.Data_Transfer[3],0,S15C.Write.RRS[RRS_Index0].MB_Reg[14],0,8)BTD(Port_Data.Data_Transfer[4],0,S15C.Write.RRS[RRS_Index0].MB_Reg[13],8,8)BTD(Port_Data.Data_Transfer[5],0,S15C.Write.RRS[RRS_Index0].MB_Reg[13],0,8)BTD(Port_Data.Data_Transfer[6],0,S15C.Write.RRS[RRS_Index0].MB_Reg[12],8,8)BTD(Port_Data.Data_Transfer[7],0,S15C.Write.RRS[RRS_Index0].MB_Reg[12],0,8)BTD(Port_Data.Data_Transfer[8],0,S15C.Write.RRS[RRS_Index0].MB_Reg[11],8,8)BTD(Port_Data.Data_Transfer[9],0,S15C.Write.RRS[RRS_Index0].MB_Reg[11],0,8)BTD(Port_Data.Data_Transfer[10],0,S15C.Write.RRS[RRS_Index0].MB_Reg[10],8,8)BTD(Port_Data.Data_Transfer[11],0,S15C.Write.RRS[RRS_Index0].MB_Reg[10],0,8)BTD(Port_Data.Data_Transfer[12],0,S15C.Write.RRS[RRS_Index0].MB_Reg[9],8,8)BTD(Port_Data.Data_Transfer[13],0,S15C.Write.RRS[RRS_Index0].MB_Reg[9],0,8)BTD(Port_Data.Data_Transfer[14],0,S15C.Write.RRS[RRS_Index0].MB_Reg[8],8,8)BTD(Port_Data.Data_Transfer[15],0,S15C.Write.RRS[RRS_Index0].MB_Reg[8],0,8)BTD(Port_Data.Data_Transfer[16],0,S15C.Write.RRS[RRS_Index0].MB_Reg[7],8,8)BTD(Port_Data.Data_Transfer[17],0,S15C.Write.RRS[RRS_Index0].MB_Reg[7],0,8)BTD(Port_Data.Data_Transfer[18],0,S15C.Write.RRS[RRS_Index0].MB_Reg[6],8,8)BTD(Port_Data.Data_Transfer[19],0,S15C.Write.RRS[RRS_Index0].MB_Reg[6],0,8)BTD(Port_Data.Data_Transfer[20],0,S15C.Write.RRS[RRS_Index0].MB_Reg[5],8,8)BTD(Port_Data.Data_Transfer[21],0,S15C.Write.RRS[RRS_Index0].MB_Reg[5],0,8)BTD(Port_Data.Data_Transfer[22],0,S15C.Write.RRS[RRS_Index0].MB_Reg[4],8,8)BTD(Port_Data.Data_Transfer[23],0,S15C.Write.RRS[RRS_Index0].MB_Reg[4],0,8)BTD(Port_Data.Data_Transfer[24],0,S15C.Write.RRS[RRS_Index0].MB_Reg[3],8,8)BTD(Port_Data.Data_Transfer[25],0,S15C.Write.RRS[RRS_Index0].MB_Reg[3],0,8)BTD(Port_Data.Data_Transfer[26],0,S15C.Write.RRS[RRS_Index0].MB_Reg[2],8,8)BTD(Port_Data.Data_Transfer[27],0,S15C.Write.RRS[RRS_Index0].MB_Reg[2],0,8)BTD(Port_Data.Data_Transfer[28],0,S15C.Write.RRS[RRS_Index0].MB_Reg[1],8,8)BTD(Port_Data.Data_Transfer[29],0,S15C.Write.RRS[RRS_Index0].MB_Reg[1],0,8)OTU(Port_Data.Port_Read.[Port])OTL(Local_Control.6);
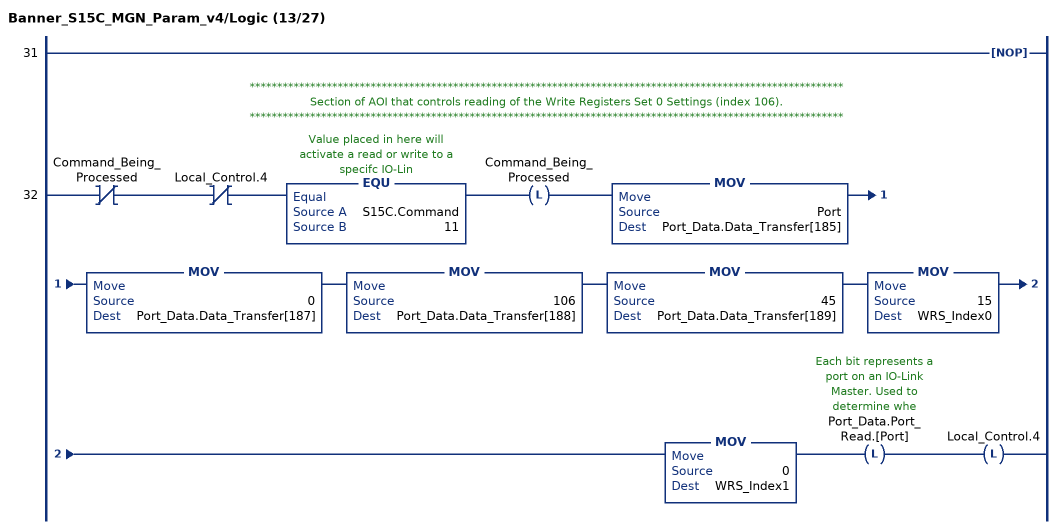
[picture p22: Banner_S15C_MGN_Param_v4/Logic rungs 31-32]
   31: NOP();
   // ************************************************************************************************************
   // Section of AOI that controls reading of the Write Registers Set 0 Settings (index 106).
   // ************************************************************************************************************
   32: XIO(Command_Being_Processed)XIO(Local_Control.4)EQU(S15C.Command,11)OTL(Command_Being_Processed)MOV(Port,Port_Data.Data_Transfer[185])MOV(0,Port_Data.Data_Transfer[187])MOV(106,Port_Data.Data_Transfer[188])MOV(45,Port_Data.Data_Transfer[189])MOV(15,WRS_Index0)MOV(0,WRS_Index1)OTL(Port_Data.Port_Read.[Port])OTL(Local_Control.4);
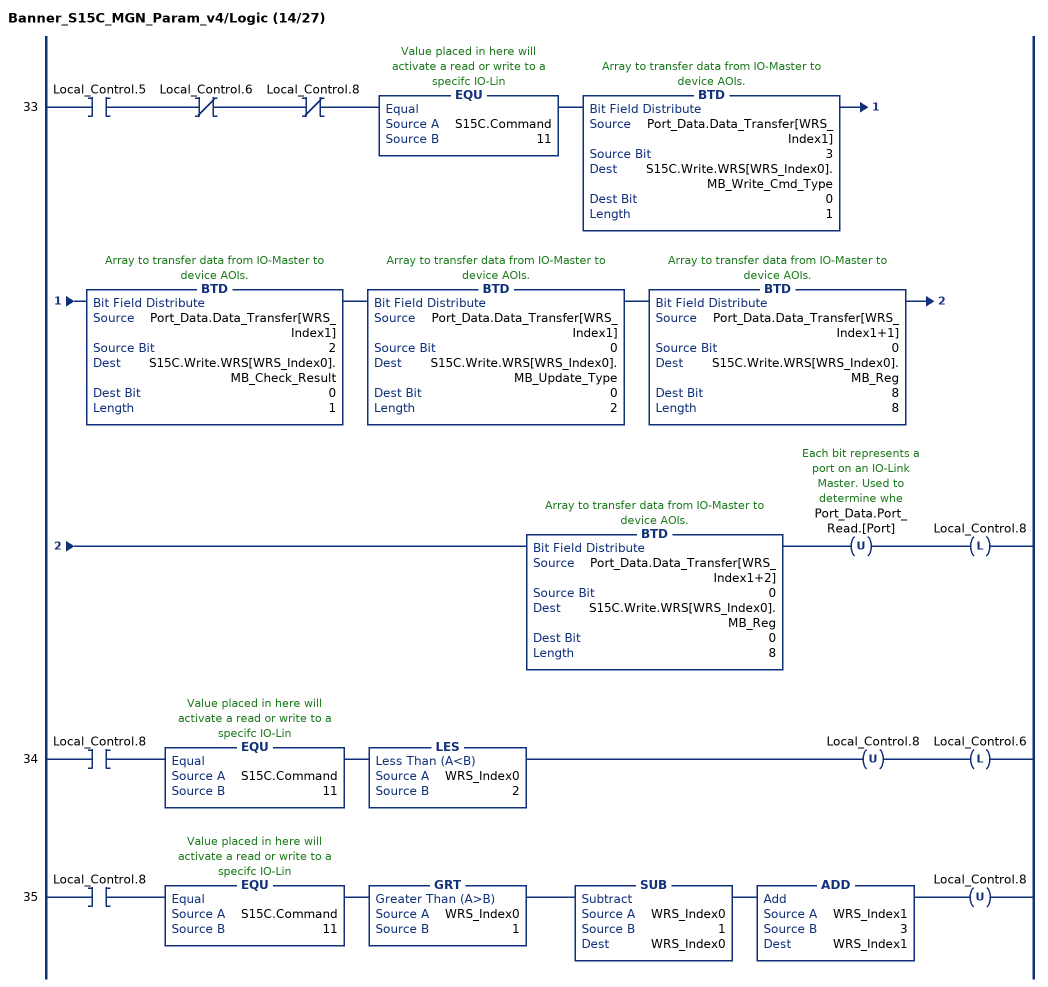
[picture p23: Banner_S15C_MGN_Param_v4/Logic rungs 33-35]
   33: XIC(Local_Control.5)XIO(Local_Control.6)XIO(Local_Control.8)EQU(S15C.Command,11)BTD(Port_Data.Data_Transfer[WRS_Index1],3,S15C.Write.WRS[WRS_Index0].MB_Write_Cmd_Type,0,1)BTD(Port_Data.Data_Transfer[WRS_Index1],2,S15C.Write.WRS[WRS_Index0].MB_Check_Result,0,1)BTD(Port_Data.Data_Transfer[WRS_Index1],0,S15C.Write.WRS[WRS_Index0].MB_Update_Type,0,2)BTD(Port_Data.Data_Transfer[WRS_Index1+1],0,S15C.Write.WRS[WRS_Index0].MB_Reg,8,8)BTD(Port_Data.Data_Transfer[WRS_Index1+2],0,S15C.Write.WRS[WRS_Index0].MB_Reg,0,8)OTU(Port_Data.Port_Read.[Port])OTL(Local_Control.8);
   34: XIC(Local_Control.8)EQU(S15C.Command,11)LES(WRS_Index0,2)OTU(Local_Control.8)OTL(Local_Control.6);
   35: XIC(Local_Control.8)EQU(S15C.Command,11)GRT(WRS_Index0,1)SUB(WRS_Index0,1,WRS_Index0)ADD(WRS_Index1,3,WRS_Index1)OTU(Local_Control.8);
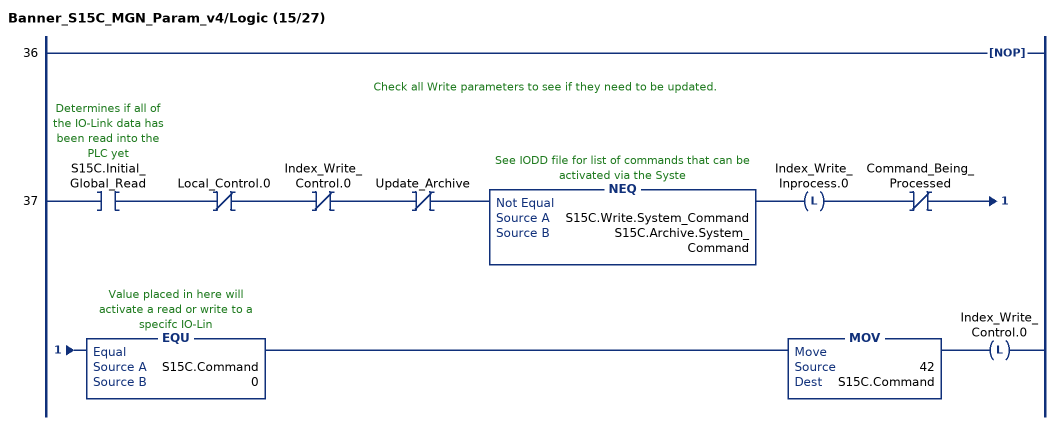
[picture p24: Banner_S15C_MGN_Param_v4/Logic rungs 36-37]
   36: NOP();
   // Check all Write parameters to see if they need to be updated.
   37: XIC(S15C.Initial_Global_Read)XIO(Local_Control.0)XIO(Index_Write_Control.0)XIO(Update_Archive)NEQ(S15C.Write.System_Command,S15C.Archive.System_Command)OTL(Index_Write_Inprocess.0)XIO(Command_Being_Processed)EQU(S15C.Command,0)MOV(42,S15C.Command)OTL(Index_Write_Control.0);
